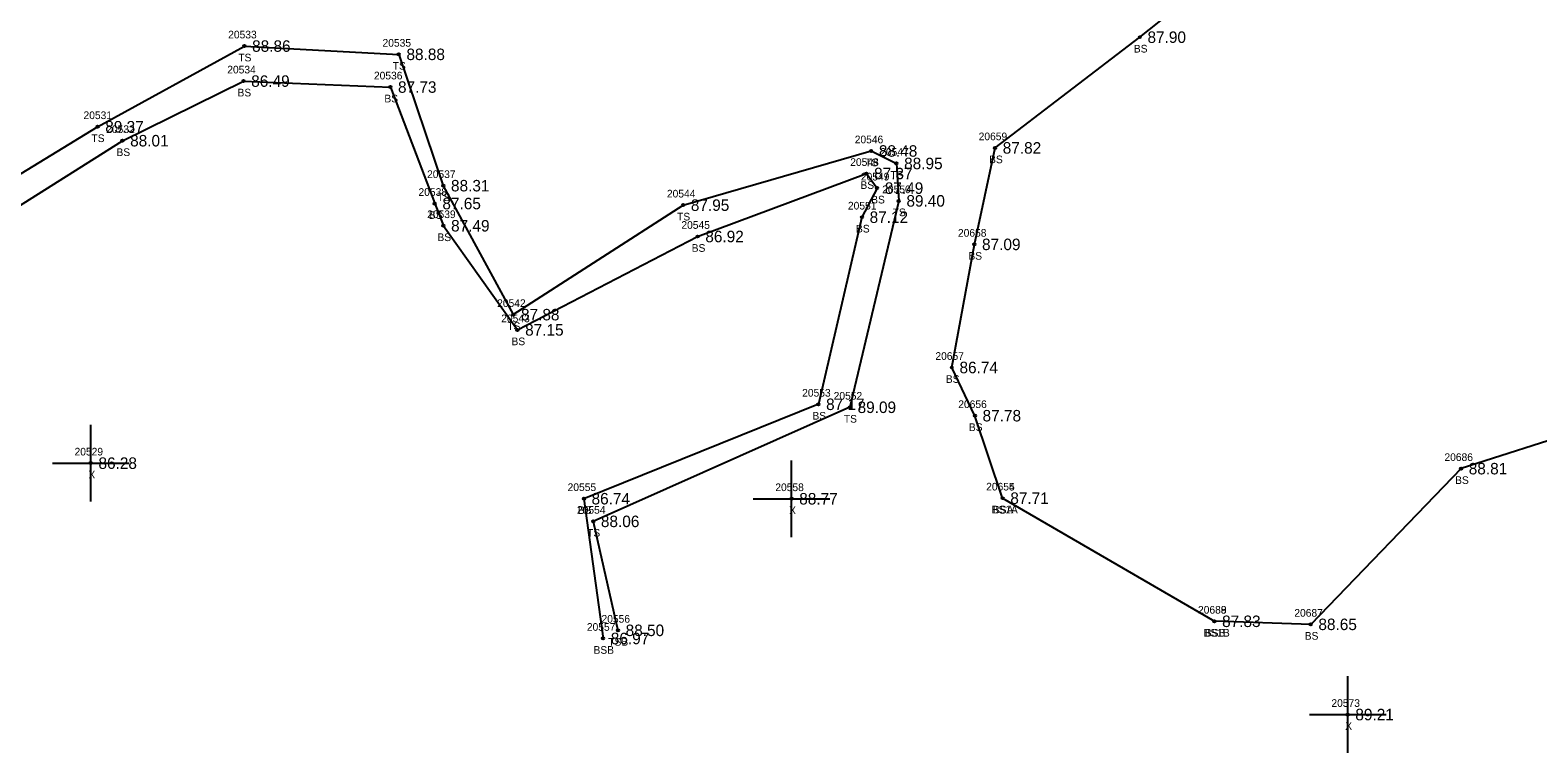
# Model space of a CAD drawing. Extents: x 2530197 to 2532051, y 935230 to 936631.
# Drawn here: x 2531512.9 to 2531709.5, y 936070.4 to 936164.7 of the extents above; entities that cross this region are included whole.
import ezdxf

# ---------------------------------------------------------------- set-up
doc = ezdxf.new("R2010")
doc.units = 0
for name, color, linetype in [('RD_DTM_BkLn2', 7, 'Continuous'), ('RD_DTM_BkLn_txCode', 7, 'Continuous'), ('RD_EX_Misc', 7, 'Continuous'), ('RD_EX_Misc_txCode', 7, 'Continuous'), ('RD_EX_TX_Misc_ELEV', 7, 'Continuous'), ('RD_SMD_Locator', 7, 'Continuous')]:
    doc.layers.add(name, color=color, linetype=linetype)

msp = doc.modelspace()

# ---------------------------------------------------------------- linework, layer by layer
at = {"layer": 'RD_DTM_BkLn2'}
msp.add_line((2531639.71, 936103.64), (2531667.33, 936087.57), dxfattribs=at)
for points in [[(2531639.71, 936103.64), (2531636.09, 936114.4), (2531633.08, 936120.69), (2531636.02, 936136.76), (2531638.72, 936149.35), (2531657.6, 936163.8), (2531681.39, 936182.74), (2531701.14, 936200.83), (2531713.8, 936233.77)], [(2531501.93, 936140.05), (2531521.67, 936152.11), (2531540.82, 936162.64), (2531560.95, 936161.56), (2531566.76, 936144.42), (2531575.89, 936127.59), (2531598.04, 936141.88), (2531622.56, 936148.95), (2531625.86, 936147.32), (2531626.16, 936142.44), (2531619.79, 936115.5), (2531586.31, 936100.61), (2531589.54, 936086.39)], [(2531503.77, 936136.95), (2531524.91, 936150.29), (2531540.7, 936158.07), (2531559.85, 936157.29), (2531565.64, 936142.09), (2531566.77, 936139.19), (2531576.43, 936125.6), (2531599.93, 936137.79), (2531621.94, 936146), (2531623.34, 936144.1), (2531621.36, 936140.31), (2531615.68, 936115.89), (2531585.09, 936103.57), (2531587.6, 936085.33)], [(2531715.02, 936112.49), (2531699.5, 936107.49), (2531679.89, 936087.17), (2531667.33, 936087.57)]]:
    msp.add_lwpolyline(points, dxfattribs=at)
at = {"layer": 'RD_EX_Misc'}
for p, q in [((2531520.78, 936103.21), (2531520.78, 936113.21)), ((2531612.18, 936098.56), (2531612.18, 936108.56)), ((2531515.78, 936108.21), (2531525.78, 936108.21)), ((2531607.18, 936103.56), (2531617.18, 936103.56)), ((2531684.71, 936070.4), (2531684.71, 936080.4)), ((2531679.71, 936075.4), (2531689.71, 936075.4))]:
    msp.add_line(p, q, dxfattribs=at)
at = {"layer": 'RD_SMD_Locator'}
for centre in [(2531657.6, 936163.8), (2531540.82, 936162.64), (2531560.95, 936161.56), (2531540.7, 936158.07), (2531559.85, 936157.29), (2531521.67, 936152.11), (2531524.91, 936150.29), (2531622.56, 936148.95), (2531638.72, 936149.35), (2531621.94, 936146), (2531625.86, 936147.32), (2531566.76, 936144.42), (2531623.34, 936144.1), (2531565.64, 936142.09), (2531598.04, 936141.88), (2531626.16, 936142.44), (2531621.36, 936140.31), (2531566.77, 936139.19), (2531599.93, 936137.79), (2531636.02, 936136.76), (2531575.89, 936127.59), (2531576.43, 936125.6), (2531633.08, 936120.69), (2531615.68, 936115.89), (2531619.79, 936115.5), (2531636.09, 936114.4), (2531520.78, 936108.21), (2531699.5, 936107.49), (2531585.09, 936103.57), (2531612.18, 936103.56), (2531639.71, 936103.64), (2531639.71, 936103.64), (2531586.31, 936100.61), (2531667.33, 936087.57), (2531667.33, 936087.57), (2531679.89, 936087.17), (2531587.6, 936085.33), (2531589.54, 936086.39), (2531684.71, 936075.4)]:
    msp.add_circle(centre, 0.15, dxfattribs=at)

# ---------------------------------------------------------------- texts
at = {"layer": 'RD_DTM_BkLn_txCode'}
for s, p in [('20533', (2531538.7, 936163.64)), ('20535', (2531558.83, 936162.56)), ('TS', (2531540.02, 936160.64)), ('BS', (2531656.82, 936161.8)), ('20534', (2531538.58, 936159.07)), ('TS', (2531560.16, 936159.56)), ('20536', (2531557.71, 936158.29)), ('BS', (2531539.92, 936156.07)), ('BS', (2531559.07, 936155.29)), ('20531', (2531519.83, 936153.11)), ('20532', (2531522.79, 936151.29)), ('TS', (2531520.87, 936150.11)), ('20546', (2531620.42, 936149.95)), ('20659', (2531636.58, 936150.35)), ('BS', (2531524.13, 936148.29)), ('20548', (2531619.83, 936147)), ('TS', (2531621.76, 936146.95)), ('20547', (2531623.74, 936148.32)), ('BS', (2531637.94, 936147.35)), ('20537', (2531564.64, 936145.42)), ('20549', (2531621.22, 936145.1)), ('TS', (2531625.06, 936145.32)), ('20538', (2531563.52, 936143.09)), ('20544', (2531595.92, 936142.88)), ('BS', (2531621.16, 936144)), ('20550', (2531624, 936143.44)), ('TS', (2531565.96, 936142.42)), ('20551', (2531619.53, 936141.31)), ('BS', (2531622.56, 936142.1)), ('20539', (2531564.65, 936140.19)), ('BS', (2531564.86, 936140.09)), ('TS', (2531597.25, 936139.88)), ('TS', (2531625.36, 936140.44)), ('BS', (2531565.99, 936137.19)), ('20545', (2531597.81, 936138.79)), ('BS', (2531620.58, 936138.31)), ('20658', (2531633.88, 936137.76)), ('BS', (2531599.15, 936135.79)), ('BS', (2531635.24, 936134.76)), ('20542', (2531573.78, 936128.59)), ('20543', (2531574.31, 936126.6)), ('TS', (2531575.1, 936125.59)), ('BS', (2531575.65, 936123.6)), ('20657', (2531630.94, 936121.69)), ('BS', (2531632.3, 936118.69)), ('20553', (2531613.56, 936116.89)), ('20552', (2531617.67, 936116.5)), ('20656', (2531633.92, 936115.4)), ('BS', (2531614.9, 936113.89)), ('TS', (2531619, 936113.5)), ('BS', (2531635.31, 936112.4)), ('20686', (2531697.33, 936108.49)), ('BS', (2531698.72, 936105.49)), ('20555', (2531582.97, 936104.57)), ('20654', (2531637.56, 936104.64)), ('20655', (2531637.56, 936104.64)), ('20554', (2531584.19, 936101.61)), ('BS', (2531584.31, 936101.57)), ('BS1A', (2531638.27, 936101.64)), ('BSA', (2531638.44, 936101.64)), ('TS', (2531585.51, 936098.61)), ('20688', (2531665.19, 936088.57)), ('20689', (2531665.19, 936088.57)), ('20687', (2531677.75, 936088.17)), ('20557', (2531585.48, 936086.33)), ('20556', (2531587.39, 936087.39)), ('TSB', (2531588.27, 936084.39)), ('BS1B', (2531665.91, 936085.57)), ('BSB', (2531666.08, 936085.57)), ('BS', (2531679.11, 936085.17)), ('BSB', (2531586.35, 936083.33))]:
    msp.add_text(s, height=1, dxfattribs=at).set_placement(p)
at = {"layer": 'RD_EX_Misc_txCode'}
for s, p in [('20529', (2531518.66, 936109.21)), ('X', (2531520.47, 936106.21)), ('20558', (2531610.06, 936104.56)), ('X', (2531611.86, 936101.56)), ('20573', (2531682.59, 936076.4)), ('X', (2531684.39, 936073.4))]:
    msp.add_text(s, height=1, dxfattribs=at).set_placement(p)
at = {"layer": 'RD_EX_TX_Misc_ELEV'}
for s, p in [('87.90', (2531658.6, 936163.05)), ('88.86', (2531541.82, 936161.89)), ('88.88', (2531561.95, 936160.81)), ('86.49', (2531541.7, 936157.32)), ('87.73', (2531560.85, 936156.54)), ('89.37', (2531522.67, 936151.36)), ('88.01', (2531525.91, 936149.54)), ('88.48', (2531623.56, 936148.2)), ('87.82', (2531639.72, 936148.6)), ('88.95', (2531626.86, 936146.57)), ('87.37', (2531622.94, 936145.25)), ('88.31', (2531567.76, 936143.67)), ('87.49', (2531624.34, 936143.35)), ('87.65', (2531566.64, 936141.34)), ('87.95', (2531599.04, 936141.13)), ('89.40', (2531627.16, 936141.69)), ('87.49', (2531567.77, 936138.44)), ('87.12', (2531622.36, 936139.56)), ('86.92', (2531600.93, 936137.04)), ('87.09', (2531637.02, 936136.01)), ('87.88', (2531576.89, 936126.84)), ('87.15', (2531577.43, 936124.85)), ('86.74', (2531634.08, 936119.94)), ('87.17', (2531616.68, 936115.14)), ('89.09', (2531620.79, 936114.75)), ('87.78', (2531637.09, 936113.65)), ('86.28', (2531521.78, 936107.46)), ('88.81', (2531700.5, 936106.74)), ('86.74', (2531586.09, 936102.82)), ('88.77', (2531613.18, 936102.81)), ('87.71', (2531640.71, 936102.89)), ('87.71', (2531640.71, 936102.89)), ('88.06', (2531587.31, 936099.86)), ('88.50', (2531590.54, 936085.64)), ('87.83', (2531668.33, 936086.82)), ('87.83', (2531668.33, 936086.82)), ('88.65', (2531680.89, 936086.42)), ('86.97', (2531588.6, 936084.58)), ('89.21', (2531685.71, 936074.65))]:
    msp.add_text(s, height=1.5, dxfattribs=at).set_placement(p)

doc.saveas('drawing.dxf')
